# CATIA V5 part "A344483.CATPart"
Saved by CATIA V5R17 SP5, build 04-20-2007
Part number: D38999_26FJ35SN
Revision: -
Definition: A344483
Nomenclature: CONNECTOR, ELEC, PLUG, CIRCULAR, THD, STR, REM CRP CONT
Source: bought
Description: CONNECTOR, ELEC, PLUG, CIRCULAR, THD, STR, REM CRP CONT
Publications: "Logical Termination.1", "Logical Pin.1", "BCP", "Point.1_generated(BCP)", "Face_generated(BCP)", "CCP", "Point.2_generated(ConnectorCnctPt1)", "Line.1_generated(ConnectorCnctPt1)", "Line.2_generated(ConnectorCnctPt1)", "BaCP", "Point.3_generated(BaCP)", "Line.3_generated(BaCP)", "Face_generated(BaCP)", "Face_generated(CCP)"
Material "Density=.1010": density 2795.67 kg/m3
Bounding box of the stored display mesh (mm): x 0 to 33.16, y -24 to 24, z -23.869 to 23.869
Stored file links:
  C:\Users\u305772\OneDrive - Gulfstream Aerospace\AD PAG\Harness\A344483.CATPart
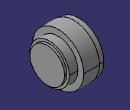
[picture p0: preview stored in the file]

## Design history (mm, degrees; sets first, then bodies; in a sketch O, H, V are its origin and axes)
Parameters
  PartNumber = "D38999_26FJ35SN"
  OtherKeywords = "CONNECTORS, ELECTRICAL, PLUG, CIRCULAR, THREADED, STRAIGHT, REMOVABLE CRIMP CONTACTS, SERIES III, METRIC"
  Comments = "ENVIRONMENT RESISTING - CONDUCTIVE PLATING, ELECTROLESS NICKEL COATING"
  CAGECode = "81349"
  WeightComment = "CALCULATED FROM CATIA"
  WeightSource = "Calculated"
  Density = 2795.67 (density)
  Volume = 4.8329e-05 (volume) {= smartVolume(Body1)}
  Weight = 0.297871 {= Volume *Density *2.20462262185}
  Shell_Front_ID = 31.92 mm
  Shell_Front_OD = 35.77 mm
  Shell_Length = 31 mm
  Shell_Rear_OD = 36.974 mm
  Coupling_Ring_Front = 3.7 mm
  Coupling_Ring_OD = 48 mm
  Coupling_Ring_Length = 19.3 mm
  Coupling_Ring_Front_OD = 46.8 mm
  Coupling_Ring_Front_OD_Length = 4.7 mm
  Insert_Front = 0.33 mm
  Keyway_Diameter = 37.85 mm
  Keyway_Width = 2.54 mm
  Grommet_Diameter = 32.31 mm
  Grommet_Length = 2.16 mm
AxisSystem1 "CCP": origin (0.33, 0, 0), X (-1, 0, 0), Y (0, -1, 0), Z (0, 0, 1)
Set1
  Point1: (33.16 {= Shell_Length+Grommet_Length}, 0, 0)
  Point2: (0.33 {= Insert_Front}, 0, 0)
  Point3: (31 {= Shell_Length}, 0, 0)
  Line1: type PtPt, FirstPoint Point2, SecondPoint Point1
  Point4: (0, 0, 2.54), relative to Point2
  Point5: (0, 0, 2.54), relative to Point3
  Line2: type PtPt, FirstPoint Point2, SecondPoint Point4
  Line3: type PtPt, FirstPoint Point3, SecondPoint Point5
Body1 (main body)
  Sketch1 on yz-plane, origin (0, 0, 0), H (0, -1, 0), V (0, 0, 1)
    arc A1 centre (0, 0) radius 17.885 from (17.885, 0) to (1.27, 17.8399) ccw
    point P1 (0, 0)
    arc A2 centre (0, 0) radius 18.925 from (1.27, 18.8823) to (-1.27, 18.8823) ccw
    point P2 (0, 0)
    line L1 (-1.27, 18.8823) -> (-1.27, 17.8399)
    line L2 (1.27, 18.8823) -> (1.27, 17.8399)
    arc A3 centre (0, 0) radius 17.885 from (-1.27, 17.8399) to (17.885, 0) ccw
    point P5 (17.885, 0)
    point P6 (17.885, 0)
    point P7 (-1.27, 17.8399)
    point P8 (1.27, 17.8399)
    radius A1 = 17.885 {= Shell_Front_OD/2}
    radius A2 = 18.925 {= Keyway_Diameter /2}
    distance L1 L2 = 2.54 {= Keyway_Width}
    distance L1 V = 1.27 {= Sketch1.distance(L1 L2)/2}
    coincidence: P1 O, P2 P1, A1 A3, P5 P6, H P5, V P1, P5 A3, P7 A1, P8 A3
    vertical: L1 V, L2 V
    perpendicularity: H L1
    concentricity: P1 A2
  Pad1: profile Sketch1, direction (1, 0, 0), length 3.7 {= Coupling_Ring_Front}
  Sketch2 on yz-plane, origin (0, 0, 0), H (0, -1, 0), V (0, 0, 1)
    circle A1 centre (0, 0) radius 23.4
    point P1 (0, 0)
    radius A1 = 23.4 {= Coupling_Ring_Front_OD /2}
    coincidence: P1 O
  Pad2: profile Sketch2, direction (1, 0, 0), length 8.4 {= Coupling_Ring_Front_OD_Length+Coupling_Ring_Front}, opposite side length -3.7 {= -Coupling_Ring_Front}
  Sketch3 on yz-plane, origin (0, 0, 0), H (0, -1, 0), V (0, 0, 1)
    circle A1 centre (0, 0) radius 24
    point P1 (0, 0)
    radius A1 = 24 {= Coupling_Ring_OD /2}
    coincidence: P1 O
  Pad3: profile Sketch3, direction (1, 0, 0), length 23 {= Coupling_Ring_Front+Coupling_Ring_Length}, opposite side length -8.4 {= -Coupling_Ring_Front-Coupling_Ring_Front_OD_Length}
  Sketch4 on yz-plane, origin (0, 0, 0), H (0, -1, 0), V (0, 0, 1)
    circle A1 centre (0, 0) radius 18.487
    point P1 (0, 0)
    radius A1 = 18.487 {= Shell_Rear_OD /2}
    coincidence: P1 O
  Pad4: profile Sketch4, direction (1, 0, 0), length 31 {= Shell_Length}, opposite side length -23 {= -Coupling_Ring_Front-Coupling_Ring_Length}
  Sketch5 on yz-plane, origin (0, 0, 0), H (0, -1, 0), V (0, 0, 1)
    circle A1 centre (0, 0) radius 16.155
    point P1 (0, 0)
    radius A1 = 16.155 {= Grommet_Diameter /2}
    coincidence: P1 O
  Pad5: profile Sketch5, direction (1, 0, 0), length 33.16 {= Shell_Length+Grommet_Length}, opposite side length -31 {= -Shell_Length}
  Sketch6 on yz-plane, origin (0, 0, 0), H (0, -1, 0), V (0, 0, 1)
    circle A1 centre (0, 0) radius 15.96
    point P1 (0, 0)
    radius A1 = 15.96 {= Shell_Front_ID /2}
    coincidence: P1 O
  Pocket1: profile Sketch6, direction (1, 0, 0), length 0.33 {= Insert_Front}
